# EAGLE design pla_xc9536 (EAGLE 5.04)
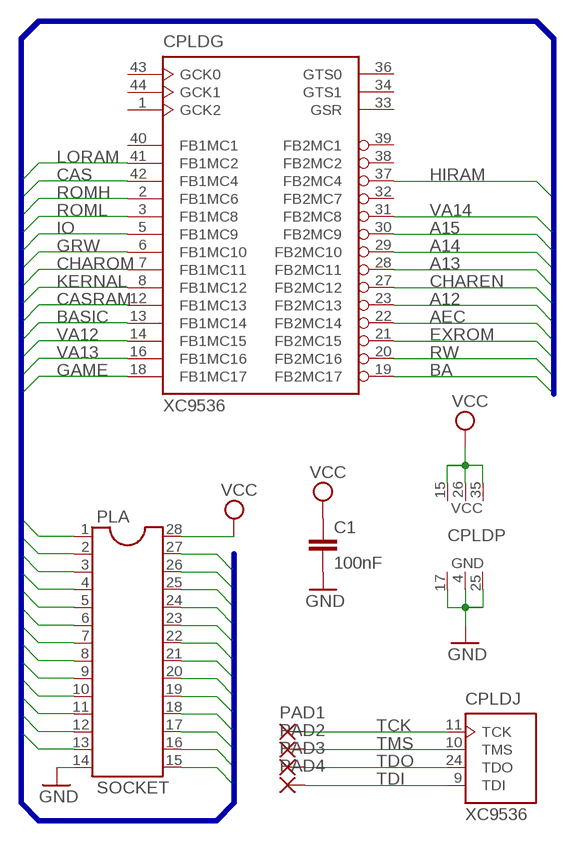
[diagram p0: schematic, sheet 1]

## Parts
C1  100nF  C-EUC1206K  [C1206K]
CPLD  XC9536  XC9536-44VQ44  [VQ44]
PAD1  SMD2  [SMD1,27-2,54]
PAD2  SMD2  [SMD1,27-2,54]
PAD3  SMD2  [SMD1,27-2,54]
PAD4  SMD2  [SMD1,27-2,54]
PLA  SOCKET  DIL28  [DIL28-6-ROUND]

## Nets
A12: CPLD.23(G:FB2MC13) PLA.27
A13: CPLD.28(G:FB2MC11) PLA.2
A14: CPLD.29(G:FB2MC10) PLA.3
A15: CPLD.30(G:FB2MC9) PLA.4
AEC: CPLD.22(G:FB2MC14) PLA.25
BA: CPLD.19(G:FB2MC17) PLA.26
BASIC: CPLD.13(G:FB1MC14) PLA.17
CAS: CPLD.42(G:FB1MC4) PLA.9
CASRAM: CPLD.12(G:FB1MC13) PLA.18
CHAREN: CPLD.27(G:FB2MC12) PLA.6
CHAROM: CPLD.7(G:FB1MC11) PLA.15
EXROM: CPLD.21(G:FB2MC15) PLA.23
GAME: CPLD.18(G:FB1MC17) PLA.22
GND: C1.2 CPLD.4(P:GND) CPLD.17(P:GND) CPLD.25(P:GND) PLA.14
GRW: CPLD.6(G:FB1MC10) PLA.13
HIRAM: CPLD.37(G:FB2MC4) PLA.7
IO: CPLD.5(G:FB1MC9) PLA.12
KERNAL: CPLD.8(G:FB1MC12) PLA.16
LORAM: CPLD.41(G:FB1MC2) PLA.8
PLA1: PLA.1
PLA19: PLA.19
ROMH: CPLD.2(G:FB1MC6) PLA.10
ROML: CPLD.3(G:FB1MC8) PLA.11
RW: CPLD.20(G:FB2MC16) PLA.24
TCK: CPLD.11(J:TCK) PAD1.1(P)
TDI: CPLD.9(J:TDI) PAD4.1(P)
TDO: CPLD.24(J:TDO) PAD3.1(P)
TMS: CPLD.10(J:TMS) PAD2.1(P)
VA12: CPLD.14(G:FB1MC15) PLA.20
VA13: CPLD.16(G:FB1MC16) PLA.21
VA14: CPLD.31(G:FB2MC8) PLA.5
VCC: C1.1 CPLD.15(P:VCC) CPLD.26(P:VCC) CPLD.35(P:VCC) PLA.28
Unconnected: CPLD.1(G:GCK2) CPLD.32(G:FB2MC7) CPLD.33(G:GSR) CPLD.34(G:GTS1) CPLD.36(G:GTS0) CPLD.38(G:FB2MC2) CPLD.39(G:FB2MC1) CPLD.40(G:FB1MC1) CPLD.43(G:GCK0) CPLD.44(G:GCK1)

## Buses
PLA[1..28]

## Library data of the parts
C1 = rcl:C-EU: CAPACITOR, European symbol
CPLD = XILINX:XC9536-44
PAD1-PAD4 = wirepad:SMD2: SMD PAD
PLA = ic-package:DIL28: Dual In Line

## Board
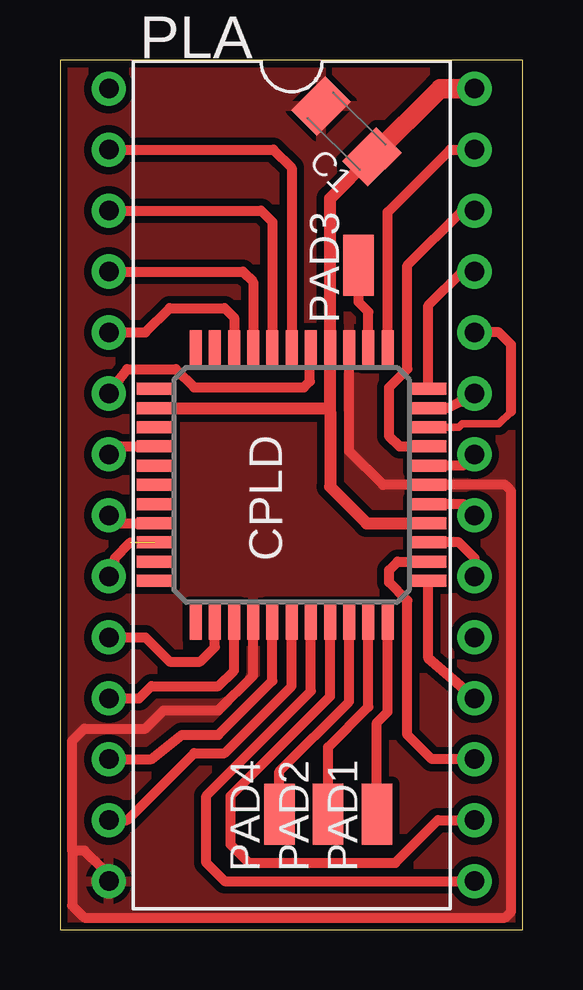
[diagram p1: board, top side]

Size 19.28 x 36.25 mm. Coordinates in mm from the lower left corner, seen from the top.
Outline: 0,0 19.28,0 19.28,36.25 0,36.25 0,0
Copper layers (1*16): Top 0.035mm / dielectric 1.5mm / Bottom 0.035mm
Design rules "steve": minimum track width 10mil, minimum drill 24mil, track to track 10mil, track to pad 10mil, pad to pad 10mil, via to via 10mil, smd to smd 10mil, copper to edge 10mil, drill to drill 10mil, minimum pad ring 10mil, minimum via ring 10mil, stop-mask expansion 4mil, vias tented up to drill 0mil, thermal gap 10mil

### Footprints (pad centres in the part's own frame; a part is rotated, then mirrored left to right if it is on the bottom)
C1206K = smd 1.5 x 2: 1 -1.5,0; 2 1.5,0
VQ44 = smd 1.5 x 0.5: 1 -5.7,4; 2 -5.7,3.2; 3 -5.7,2.4; 4 -5.7,1.6; 5 -5.7,0.8; 6 -5.7,0; 7 -5.7,-0.8; 8 -5.7,-1.6; 9 -5.7,-2.4; 10 -5.7,-3.2; 11 -5.7,-4; 23 5.7,-4; 24 5.7,-3.2; 25 5.7,-2.4; 26 5.7,-1.6; 27 5.7,-0.8; 28 5.7,0; 29 5.7,0.8; 30 5.7,1.6; 31 5.7,2.4; 32 5.7,3.2; 33 5.7,4 | smd 0.5 x 1.5: 12 -4,-5.7; 13 -3.2,-5.7; 14 -2.4,-5.7; 15 -1.6,-5.7; 16 -0.8,-5.7; 17 0,-5.7; 18 0.8,-5.7; 19 1.6,-5.7; 20 2.4,-5.7; 21 3.2,-5.7; 22 4,-5.7; 34 4,5.7; 35 3.2,5.7; 36 2.4,5.7; 37 1.6,5.7; 38 0.8,5.7; 39 0,5.7; 40 -0.8,5.7; 41 -1.6,5.7; 42 -2.4,5.7; 43 -3.2,5.7; 44 -4,5.7
SMD1,27-2,54 = smd 1.27 x 2.54: 1 0,0
DIL28-6-ROUND = drill 0.813 pad 1.422 round: 1 -15.24,-7.62; 2 -12.7,-7.62; 3 -10.16,-7.62; 4 -7.62,-7.62; 5 -5.08,-7.62; 6 -2.54,-7.62; 7 0,-7.62; 8 2.54,-7.62; 9 5.08,-7.62; 10 7.62,-7.62; 11 10.16,-7.62; 12 12.7,-7.62; 13 15.24,-7.62; 14 17.78,-7.62; 15 17.78,7.62; 16 15.24,7.62; 17 12.7,7.62; 18 10.16,7.62; 19 7.62,7.62; 20 5.08,7.62; 21 2.54,7.62; 22 0,7.62; 23 -2.54,7.62; 24 -5.08,7.62; 25 -7.62,7.62; 26 -10.16,7.62; 27 -12.7,7.62; 28 -15.24,7.62

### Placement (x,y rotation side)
C1  11.94,33.27 135 top
CPLD  9.65,18.54 90 top
PAD1  13.21,4.83 0 top
PAD2  11.18,4.83 0 top
PAD3  12.45,27.69 0 top
PAD4  9.14,4.83 0 top
PLA  9.65,19.81 270 top

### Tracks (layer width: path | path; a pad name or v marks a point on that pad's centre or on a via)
A12
  Top 0.406: CPLD.23 13.65,29.91 16.26,32.51 PLA.27
A13
  Top 0.406: CPLD.28 9.65,31.75 8.89,32.51 PLA.2
A14
  Top 0.406: CPLD.29 8.85,29.5 8.38,29.97 PLA.3
A15
  Top 0.406: CPLD.30 8.05,27 7.62,27.43 PLA.4
AEC
  Top 0.406: CPLD.22 15.35,26.02 16.76,27.43 PLA.25
BA
  Top 0.406: CPLD.19 14.15,20.14 13.72,20.57 13.72,22.61 14.48,23.37 14.48,27.69 16.76,29.97 PLA.26
BASIC
  Top 0.406: CPLD.13 14.07,15.34 13.72,14.99 13.72,14.48 14.48,13.72 14.48,8.13 15.49,7.11 PLA.17
CAS  (1 unrouted)
  Top 0.406: 2.93,16.14 2.29,15.49 2.29,14.99 PLA.9
CASRAM
  Top 0.406: CPLD.12 15.35,11.32 PLA.18
CHAREN
  Top 0.406: CPLD.27 10.41,24.2 10.41,22.86 10.16,22.61 5.59,22.61 4.83,23.37 2.79,23.37 PLA.6
CHAROM
  Top 0.406: CPLD.7 10.45,9.94 6.1,5.59 6.1,2.79 6.86,2.03 PLA.15
EXROM
  Top 0.406: CPLD.21 16.15,21.74 16.66,22 PLA.23
GAME
  Top 0.406: CPLD.18 16.8,19.34 16.8,19.6 PLA.22
GND
  Top 0.406: 0.51,3.3 1.02,3.3 1.78,2.54 PLA.14 | 0.51,3.3 0.51,1.02 1.02,0.51 18.54,0.51 18.8,0.76 18.8,18.29 18.54,18.54 CPLD.17 13.46,18.54 12.05,19.95 CPLD.25 | CPLD.4 8.05,10.59 6.6,9.14 4.32,9.14 3.56,8.38 1.02,8.38 0.51,7.87 0.51,3.3
  pour Top (isolate 0.305): 0,36.32 19.56,36.32 19.56,-0.25 0,-0.25
GRW
  Top 0.406: CPLD.6 9.65,10.16 6.86,7.37 5.59,7.37 2.79,4.57 PLA.13
HIRAM
  Top 0.406: CPLD.37 2.36,20.14 PLA.7
IO
  Top 0.406: CPLD.5 8.85,10.38 6.6,8.13 5.08,8.13 3.81,7.11 PLA.12
KERNAL
  Top 0.406: CPLD.8 11.25,9.73 7.11,5.59 7.11,3.56 7.87,2.79 13.97,2.79 15.75,4.57 PLA.16
LORAM
  Top 0.406: CPLD.41 2.36,16.94 PLA.8
ROMH
  Top 0.406: CPLD.2 6.45,11.79 5.84,11.18 4.57,11.18 3.56,12.19 PLA.10
ROML
  Top 0.406: CPLD.3 7.25,10.81 6.6,10.16 3.81,10.16 3.3,9.65 PLA.11
RW
  Top 0.305: CPLD.20 16.62,20.94 16.76,21.08 18.29,21.08 18.8,21.59
  Top 0.406: 18.8,21.59 18.8,24.38 18.29,24.89 PLA.24
TCK
  Top 0.406: CPLD.11 13.65,9.08 13.21,8.64 PAD1.1
TDI
  Top 0.406: CPLD.9 12.05,9.51 9.14,6.6 PAD4.1
TDO
  Top 0.406: CPLD.24 12.85,25.76 12.45,26.16 PAD3.1
TMS
  Top 0.406: CPLD.10 12.85,9.3 11.18,7.62 PAD2.1
VA12
  Top 0.406: CPLD.14 16.62,16.14 17.27,15.49 PLA.20
VA13
  Top 0.406: CPLD.16 16.8,17.74 16.8,17.49 PLA.21
VA14
  Top 0.406: CPLD.31 7.25,25.51 6.86,25.91 4.57,25.91 3.56,24.89 PLA.5
VCC
  Top 0.406: 11.1,21.74 11.25,21.59
  Top 0.508: CPLD.15 12.78,16.94 11.25,18.47 11.25,21.59 CPLD.26 11.25,30.47 C1.1 | CPLD.35 11.1,21.74
  Top 0.813: PLA.28 15.84,35.05 C1.1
